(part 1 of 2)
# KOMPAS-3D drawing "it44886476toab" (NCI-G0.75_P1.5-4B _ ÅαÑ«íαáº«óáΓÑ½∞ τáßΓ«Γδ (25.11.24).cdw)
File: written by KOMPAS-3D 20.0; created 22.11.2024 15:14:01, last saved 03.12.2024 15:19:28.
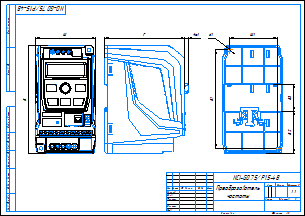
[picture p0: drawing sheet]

Sheet 1: A3, landscape

Document properties: Полное имя файла: P:\INSTART\Технический отдел\ОР\Прочие задачи\КД на номенклатурный ряд\КД на типоразмеры ПЧ\NCI\NCI-G0.75_P1.5-4B\NCI-G0.75_P1.5-4B _ Преобразователь частоты (25.11.24).cdw; Автор: admin

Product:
- Part/product: it44886476toab
    Масса: 2.32322
  - Body: Тело 2
      Масса: 0.00113358
  - Body: Тело 3
      Масса: 0.00113358
  - Body: Тело 4
      Масса: 0.000355433
  - Body: Тело 6
      Масса: 0.000355433
  - Body: Тело 7
      Масса: 0.000703761
  - Body: Тело 8
      Масса: 0.000703761
  - Body: Тело 10
      Масса: 0.0160396
  - Body: Тело 11
      Масса: 0.000703761
  - Body: Тело 13
      Масса: 0.000703761
  - Body: Тело 14
      Масса: 0.000703761
  - Body: Тело 18
      Масса: 0.0117014
  - Body: Тело 20
      Масса: 0.120334
  - Body: Тело 21
      Масса: 0.0864411
  - Body: Тело 22
      Масса: 0.0636504
  - Body: Тело 25
      Масса: 0.00135688
  - Body: Тело 26
      Масса: 0.00135688
  - Body: Тело 27
      Масса: 0.00135688
  - Body: Тело 30
      Масса: 0.000935996
  - Body: Тело 34
      Масса: 0.00831628
  - Body: Тело 36
      Масса: 0.0668131
  - Body: Тело 37
      Масса: 0.0343584
  - Body: Тело 39
      Масса: 0.0119524
  - Body: Тело 40
      Масса: 0.0119524
  - Body: Тело 42
      Масса: 0.0119524
  - Body: Тело 43
      Масса: 0.0119524
  - Body: Тело 46
      Масса: 0.0119034
  - Body: Тело 47
      Масса: 0.551587
  - Body: Тело 51
      Масса: 1.32696e-05
  - Body: Тело 54
      Масса: 1.32696e-05
  - Body: Тело 55
      Масса: 1.32696e-05
  - Body: Тело 56
      Масса: 1.32696e-05
  - Body: Тело 58
      Масса: 1.32696e-05
  - Body: Тело 61
      Масса: 1.32696e-05
  - Body: Тело 57
      Масса: 1.32696e-05
  - Body: Тело 63
      Масса: 1.65581e-05
  - Body: Тело 66
      Масса: 1.65581e-05
  - Body: Тело 67
      Масса: 1.65581e-05
  - Body: Тело 68
      Масса: 1.65581e-05
  - Body: Тело 69
      Масса: 1.65581e-05
  - Body: Тело 73
      Масса: 1.65581e-05
  - Body: Тело 48
      Масса: 0.00853877
  - Body: Тело 74
      Масса: 1.65581e-05
  - Body: Тело 78
      Масса: 1.65581e-05
  - Body: Тело 79
      Масса: 1.32696e-05
  - Body: Тело 80
      Масса: 1.32696e-05
  - Body: Тело 82
      Масса: 1.32696e-05
  - Body: Тело 83
      Масса: 1.32696e-05
  - Body: Тело 84
      Масса: 1.32696e-05
  - Body: Тело 87
      Масса: 0.000966482
  - Body: Тело 88
      Масса: 0.000873873
  - Body: Тело 15
      Масса: 0.000703761
  - Body: Тело 91
      Масса: 0.0246688
  - Body: Тело 92
      Масса: 3.83377e-05
  - Body: Тело 94
      Масса: 0.00554276
  - Body: Тело 96
      Масса: 0.00181049
  - Body: Тело 101
      Масса: 1.32696e-05
  - Body: Тело 90
      Масса: 0.000966482
  - Body: Тело 102
      Масса: 1.32696e-05
  - Body: Тело 104
      Масса: 1.32696e-05
  - Body: Тело 107
      Масса: 1.32696e-05
  - Body: Тело 108
      Масса: 1.32696e-05
  - Body: Тело 111
      Масса: 0.000194606
  - Body: Тело 115
      Масса: 0.000413213
  - Body: Тело 123
      Масса: 1.65581e-05
  - Body: Тело 127
      Масса: 1.32696e-05
  - Body: Тело 128
      Масса: 1.32696e-05
  - Body: Тело 129
      Масса: 1.32696e-05
  - Body: Тело 112
      Масса: 0.000413213
  - Body: Тело 130
      Масса: 1.32696e-05
  - Body: Тело 16
      Масса: 0.000703761
  - Body: Тело 131
      Масса: 1.32696e-05
  - Body: Тело 132
      Масса: 1.32696e-05
  - Body: Тело 133
      Масса: 1.32696e-05
  - Body: Тело 38
      Масса: 0.00631989
  - Body: Тело 135
      Масса: 1.32696e-05
  - Body: Тело 136
      Масса: 1.32696e-05
  - Body: Тело 142
      Масса: 0.000213463
  - Body: Тело 144
      Масса: 1.32696e-05
  - Body: Тело 62
      Масса: 1.32696e-05
  - Body: Тело 24
      Масса: 0.0110484
  - Body: Тело 147
      Масса: 1.32696e-05
  - Body: Тело 148
      Масса: 1.32696e-05
  - Body: Тело 154
      Масса: 1.32696e-05
  - Body: Тело 156
      Масса: 1.32696e-05
  - Body: Тело 158
      Масса: 1.32696e-05
  - Body: Тело 116
      Масса: 0.000413213
  - Body: Тело 159
      Масса: 1.32696e-05
  - Body: Тело 165
      Масса: 1.65581e-05
  - Body: Тело 166
      Масса: 1.32696e-05
  - Body: Тело 140
      Масса: 0.000213463
  - Body: Тело 169
      Масса: 1.32696e-05
  - Body: Тело 171
      Масса: 1.32696e-05
  - Body: Тело 153
      Масса: 1.32696e-05
  - Body: Тело 172
      Масса: 1.65581e-05
  - Body: Тело 173
      Масса: 1.32696e-05
  - Body: Тело 137
      Масса: 1.32696e-05
  - Body: Тело 45
      Масса: 0.0267013
  - Body: Тело 175
      Масса: 1.32696e-05
  - Body: Тело 177
      Масса: 1.32696e-05
  - Body: Тело 50
      Масса: 0.00101975
  - Body: Тело 44
      Масса: 0.0119524
  - Body: Тело 178
      Масса: 1.32696e-05
  - Body: Тело 179
      Масса: 1.32696e-05
  - Body: Тело 181
      Масса: 1.32696e-05
  - Body: Тело 182
      Масса: 1.32696e-05
  - Body: Тело 183
      Масса: 1.32696e-05
  - Body: Тело 188
      Масса: 1.32696e-05
  - Body: Тело 189
      Масса: 1.32696e-05
  - Body: Тело 192
      Масса: 1.32696e-05
  - Body: Тело 195
      Масса: 1.32696e-05
  - Body: Тело 197
      Масса: 1.32696e-05
  - Body: Тело 198
      Масса: 1.32696e-05
  - Body: Тело 199
      Масса: 1.32696e-05
  - Body: Тело 29
      Масса: 0.00135688
  - Body: Тело 201
      Масса: 1.32696e-05
  - Body: Тело 202
      Масса: 1.32696e-05
  - Body: Тело 205
      Масса: 1.32696e-05
  - Body: Тело 208
      Масса: 1.7366e-05
  - Body: Тело 209
      Масса: 1.32696e-05
  - Body: Тело 211
      Масса: 1.32696e-05
  - Body: Тело 212
      Масса: 1.32696e-05
  - Body: Тело 214
      Масса: 1.32696e-05
  - Body: Тело 9
      Масса: 0.000703761
  - Body: Тело 215
      Масса: 1.65581e-05
  - Body: Тело 217
      Масса: 1.32696e-05
  - Body: Тело 218
      Масса: 1.32696e-05
  - Body: Тело 219
      Масса: 1.32696e-05
  - Body: Тело 220
      Масса: 1.32696e-05
  - Body: Тело 221
      Масса: 1.65581e-05
  - Body: Тело 223
      Масса: 1.32696e-05
  - Body: Тело 162
      Масса: 1.65581e-05
  - Body: Тело 224
      Масса: 1.32696e-05
  - Body: Тело 228
      Масса: 1.32696e-05
  - Body: Тело 184
      Масса: 1.32696e-05
  - Body: Тело 230
      Масса: 1.32696e-05
  - Body: Тело 231
      Масса: 0.00398049
  - Body: Тело 232
      Масса: 5.48304e-05
  - Body: Тело 233
      Масса: 1.7366e-05
  - Body: Тело 1
      Масса: 0.00113358
  - Body: Тело 237
      Масса: 1.7366e-05
  - Body: Тело 141
      Масса: 0.000213463
  - Body: Тело 241
      Масса: 0.000424983
  - Body: Тело 65
      Масса: 1.65581e-05
  - Body: Тело 242
      Масса: 1.65581e-05
  - Body: Тело 243
      Масса: 1.65581e-05
  - Body: Тело 245
      Масса: 1.65581e-05
  - Body: Тело 234
      Масса: 1.7366e-05
  - Body: Тело 114
      Масса: 0.000413213
  - Body: Тело 19
      Масса: 0.0117014
  - Body: Тело 248
      Масса: 1.7366e-05
  - Body: Тело 249
      Масса: 1.7366e-05
  - Body: Тело 250
      Масса: 1.7366e-05
  - Body: Тело 254
      Масса: 1.32696e-05
  - Body: Тело 255
      Масса: 1.7366e-05
  - Body: Тело 119
      Масса: 0.000413213
  - Body: Тело 256
      Масса: 1.7366e-05
  - Body: Тело 167
      Масса: 1.32696e-05
  - Body: Тело 260
      Масса: 1.7366e-05
  - Body: Тело 261
      Масса: 3.83377e-05
  - Body: Тело 170
      Масса: 1.32696e-05
  - Body: Тело 463
      Масса: 0.000404362
  - Body: Тело 226
      Масса: 0.000413213
  - Body: Тело 464
      Масса: 0.00829425
  - Body: Тело 268
      Масса: 5.48304e-05
  - Body: Тело 467
      Масса: 0.00436982
  - Body: Тело 475
      Масса: 1.51773e-05
  - Body: Тело 451
      Масса: 6.34685e-05
  - Body: Тело 478
      Масса: 1.51773e-05
  - Body: Тело 465
      Масса: 0.00829114
  - Body: Тело 383
      Масса: 0.000340816
  - Body: Тело 125
      Масса: 1.65581e-05
  - Body: Тело 643
      Масса: 0.000158536
  - Body: Тело 514
      Масса: 1.51773e-05
  - Body: Тело 483
      Масса: 1.51773e-05
  - Body: Тело 486
      Масса: 0.000158536
  - Body: Тело 581
      Масса: 1.65581e-05
  - Body: Тело 490
      Масса: 1.51773e-05
  - Body: Тело 491
      Масса: 1.65581e-05
  - Body: Тело 433
      Масса: 0.000118347
  - Body: Тело 496
      Масса: 1.51773e-05
  - Body: Тело 437
      Масса: 0.00113358
  - Body: Тело 535
      Масса: 1.52051e-05
  - Body: Тело 498
      Масса: 1.51773e-05
  - Body: Тело 60
      Масса: 1.32696e-05
  - Body: Тело 369
      Масса: 1.32696e-05
  - Body: Тело 501
      Масса: 1.51773e-05
  - Body: Тело 503
      Масса: 1.51773e-05
  - Body: Тело 447
      Масса: 0.000307437
  - Body: Тело 187
      Масса: 1.32696e-05
  - Body: Тело 12
      Масса: 0.000703761
  - Body: Тело 507
      Масса: 1.51773e-05
  - Body: Тело 174
      Масса: 1.65581e-05
  - Body: Тело 587
      Масса: 1.32696e-05
  - Body: Тело 155
      Масса: 1.32696e-05
  - Body: Тело 512
      Масса: 1.51773e-05
  - Body: Тело 515
      Масса: 0.00507372
  - Body: Тело 510
      Масса: 1.51773e-05
  - Body: Тело 487
      Масса: 1.65581e-05
  - Body: Тело 432
      Масса: 0.000118347
  - Body: Тело 524
      Масса: 1.65581e-05
  - Body: Тело 637
      Масса: 1.51773e-05
  - Body: Тело 519
      Масса: 1.7366e-05
  - Body: Тело 427
      Масса: 1.32696e-05
  - Body: Тело 520
      Масса: 5.48304e-05
  - Body: Тело 326
      Масса: 1.32696e-05
  - Body: Тело 509
      Масса: 1.51773e-05
  - Body: Тело 571
      Масса: 0.00166679
  - Body: Тело 521
      Масса: 1.32696e-05
  - Body: Тело 522
      Масса: 1.65581e-05
  - Body: Тело 49
      Масса: 0.00944
  - Body: Тело 319
      Масса: 1.32696e-05
  - Body: Тело 458
      Масса: 1.51773e-05
  - Body: Тело 523
      Масса: 0.000255388
  - Body: Тело 191
      Масса: 1.32696e-05
  - Body: Тело 590
      Масса: 1.32696e-05
  - Body: Тело 599
      Масса: 7.12116e-06
  - Body: Тело 528
      Масса: 0.000141095
  - Body: Тело 64
      Масса: 1.65581e-05
  - Body: Тело 468
      Масса: 0.0253857
  - Body: Тело 216
      Масса: 0.000280294
  - Body: Тело 443
      Масса: 0.00113358
  - Body: Тело 239
      Масса: 5.48304e-05
  - Body: Тело 200
      Масса: 1.32696e-05
  - Body: Тело 579
      Масса: 0.00017125
  - Body: Тело 529
      Масса: 5.61948e-05
  - Body: Тело 493
      Масса: 1.51773e-05
  - Body: Тело 532
      Масса: 5.61948e-05
  - Body: Тело 343
      Масса: 0.00166679
  - Body: Тело 616
      Масса: 1.63919e-05
  - Body: Тело 462
      Масса: 0.000404362
  - Body: Тело 542
      Масса: 0.000158536
  - Body: Тело 543
      Масса: 0.000158536
  - Body: Тело 615
      Масса: 1.63919e-05
  - Body: Тело 149
      Масса: 1.32696e-05
  - Body: Тело 146
      Масса: 1.32696e-05
  - Body: Тело 469
      Масса: 0.0113891
  - Body: Тело 544
      Масса: 0.000158536
  - Body: Тело 295
      Масса: 1.65581e-05
  - Body: Тело 120
      Масса: 0.000413213
  - Body: Тело 352
      Масса: 2.90876e-05
  - Body: Тело 502
      Масса: 1.51773e-05
  - Body: Тело 461
      Масса: 0.000404362
  - Body: Тело 145
      Масса: 1.32696e-05
  - Body: Тело 545
      Масса: 1.51773e-05
  - Body: Тело 506
      Масса: 1.51773e-05
  - Body: Тело 71
      Масса: 1.65581e-05
  - Body: Тело 41
      Масса: 0.0119524
  - Body: Тело 547
      Масса: 0.000255388
  - Body: Тело 614
      Масса: 1.63919e-05
  - Body: Тело 257
      Масса: 1.7366e-05
  - Body: Тело 549
      Масса: 0.000255388
  - Body: Тело 204
      Масса: 1.32696e-05
  - Body: Тело 35
      Масса: 0.262997
  - Body: Тело 421
      Масса: 1.7366e-05
  - Body: Тело 258
      Масса: 1.7366e-05
  - Body: Тело 504
      Масса: 1.51773e-05
  - Body: Тело 366
      Масса: 1.7366e-05
  - Body: Тело 592
      Масса: 7.12116e-06
  - Body: Тело 32
      Масса: 0.0135217
  - Body: Тело 550
      Масса: 0.000255388
  - Body: Тело 157
      Масса: 1.32696e-05
  - Body: Тело 126
      Масса: 0.000512664
  - Body: Тело 314
      Масса: 1.7366e-05
  - Body: Тело 247
      Масса: 1.7366e-05
  - Body: Тело 23
      Масса: 0.0243258
  - Body: Тело 595
      Масса: 1.32696e-05
  - Body: Тело 534
      Масса: 1.32696e-05
  - Body: Тело 552
      Масса: 4.06595e-05
  - Body: Тело 176
      Масса: 1.32696e-05
  - Body: Тело 553
      Масса: 4.06595e-05
  - Body: Тело 28
      Масса: 0.00135688
  - Body: Тело 330
      Масса: 1.7366e-05
  - Body: Тело 190
      Масса: 1.32696e-05
  - Body: Тело 416
      Масса: 1.7366e-05
  - Body: Тело 435
      Масса: 0.00113358
  - Body: Тело 634
      Масса: 1.51773e-05
  - Body: Тело 555
      Масса: 0.00166679
  - Body: Тело 556
      Масса: 0.00166679
  - Body: Тело 602
      Масса: 5.61948e-05
  - Body: Тело 630
      Масса: 1.51773e-05
  - Body: Тело 558
      Масса: 0.00726683
  - Body: Тело 505
      Масса: 1.51773e-05
  - Body: Тело 500
      Масса: 1.51773e-05
  - Body: Тело 72
      Масса: 1.65581e-05
  - Body: Тело 279
      Масса: 1.32696e-05
  - Body: Тело 298
      Масса: 3.64495e-05
  - Body: Тело 168
      Масса: 1.32696e-05
  - Body: Тело 495
      Масса: 1.51773e-05
  - Body: Тело 336
      Масса: 3.64028e-05
  - Body: Тело 629
      Масса: 1.51773e-05
  - Body: Тело 263
      Масса: 1.7366e-05
  - Body: Тело 610
      Масса: 0.00166679
  - Body: Тело 609
      Масса: 1.7366e-05
  - Body: Тело 596
      Масса: 1.32696e-05
  - Body: Тело 538
      Масса: 1.51773e-05
  - Body: Тело 476
      Масса: 1.51773e-05
  - Body: Тело 227
      Масса: 1.32696e-05
  - Body: Тело 382
      Масса: 5.48304e-05
  - Body: Тело 470
      Масса: 0.00329329
  - Body: Тело 341
      Масса: 0.00166679
  - Body: Тело 426
      Масса: 1.32696e-05
  - Body: Тело 513
      Масса: 1.51773e-05
  - Body: Тело 236
      Масса: 1.7366e-05
  - Body: Тело 585
      Масса: 4.06595e-05
  - Body: Тело 649
      Масса: 0.00426189
  - Body: Тело 531
      Масса: 5.61948e-05
  - Body: Тело 627
      Масса: 0.000255388
  - Body: Тело 621
      Масса: 1.32696e-05
  - Body: Тело 349
      Масса: 1.7366e-05
  - Body: Тело 580
      Масса: 1.32696e-05
  - Body: Тело 631
      Масса: 1.51773e-05
  - Body: Тело 185
      Масса: 1.32696e-05
  - Body: Тело 117
      Масса: 0.000413213
  - Body: Тело 623
      Масса: 1.32696e-05
  - Body: Тело 605
      Масса: 5.61948e-05
  - Body: Тело 400
      Масса: 1.7366e-05
  - Body: Тело 139
      Масса: 0.000194606
  - Body: Тело 492
      Масса: 1.51773e-05
  - Body: Тело 612
      Масса: 0.000158536
  - Body: Тело 403
      Масса: 1.7366e-05
  - Body: Тело 460
      Масса: 3.90329e-05
  - Body: Тело 608
      Масса: 0.00166679
  - Body: Тело 635
      Масса: 1.65581e-05
  - Body: Тело 264
      Масса: 1.7366e-05
  - Body: Тело 646
      Масса: 0.000137594
  - Body: Тело 110
      Масса: 1.32696e-05
  - Body: Тело 302
      Масса: 1.65581e-05
  - Body: Тело 151
      Масса: 1.65581e-05
  - Body: Тело 497
      Масса: 1.51773e-05
  - Body: Тело 620
      Масса: 1.7366e-05
  - Body: Тело 518
      Масса: 0.00166679
  - Body: Тело 633
      Масса: 1.51773e-05
  - Body: Тело 564
      Масса: 4.06595e-05
  - Body: Тело 641
      Масса: 3.90329e-05
  - Body: Тело 494
      Масса: 1.51773e-05
  - Body: Тело 280
      Масса: 1.32696e-05
  - Body: Тело 81
      Масса: 1.32696e-05
  - Body: Тело 482
      Масса: 1.51773e-05
  - Body: Тело 594
      Масса: 1.32696e-05
  - Body: Тело 561
      Масса: 1.65581e-05
  - Body: Тело 253
      Масса: 1.7366e-05
  - Body: Тело 164
      Масса: 1.32696e-05
  - Body: Тело 525
      Масса: 0.000213463
  - Body: Тело 618
      Масса: 1.63919e-05
  - Body: Тело 642
      Масса: 3.90329e-05
  - Body: Тело 113
      Масса: 0.000413213
  - Body: Тело 546
      Масса: 0.000255388
  - Body: Тело 225
      Масса: 1.32696e-05
  - Body: Тело 138
      Масса: 2.23009e-05
  - Body: Тело 284
      Масса: 1.7366e-05
  - Body: Тело 485
      Масса: 0.000158536
  - Body: Тело 456
      Масса: 1.51773e-05
  - Body: Тело 489
      Масса: 1.51773e-05
  - Body: Тело 638
      Масса: 1.7366e-05
  - Body: Тело 563
      Масса: 4.06595e-05
  - Body: Тело 566
      Масса: 1.32696e-05
  - Body: Тело 160
      Масса: 1.32696e-05
  - Body: Тело 511
      Масса: 1.51773e-05
  - Body: Тело 541
      Масса: 0.000158536
  - Body: Тело 306
      Масса: 1.65581e-05
  - Body: Тело 356
      Масса: 1.65581e-05
  - Body: Тело 591
      Масса: 7.12116e-06
  - Body: Тело 313
      Масса: 1.7366e-05
  - Body: Тело 471
      Масса: 0.00329327
  - Body: Тело 289
      Масса: 1.7366e-05
  - Body: Тело 607
      Масса: 1.32696e-05
  - Body: Тело 603
      Масса: 5.61948e-05
  - Body: Тело 600
      Масса: 5.61948e-05
  - Body: Тело 121
      Масса: 0.000413213
  - Body: Тело 624
      Масса: 1.32696e-05
  - Body: Тело 527
      Масса: 0.000141095
  - Body: Тело 622
      Масса: 1.32696e-05
  - Body: Тело 484
      Масса: 0.000158536
  - Body: Тело 601
      Масса: 5.61948e-05
  - Body: Тело 296
      Масса: 3.6965e-05
  - Body: Тело 540
      Масса: 1.51773e-05
  - Body: Тело 210
      Масса: 1.32696e-05
  - Body: Тело 611
      Масса: 0.000158536
  - Body: Тело 161
      Масса: 1.32696e-05
  - Body: Тело 650
      Масса: 0.00426189
  - Body: Тело 604
      Масса: 5.61948e-05
  - Body: Тело 342
      Масса: 0.00166679
  - Body: Тело 251
      Масса: 1.7366e-05
  - Body: Тело 194
      Масса: 1.32696e-05
  - Body: Тело 568
      Масса: 1.32696e-05
  - Body: Тело 150
      Масса: 1.32696e-05
  - Body: Тело 640
      Масса: 1.63919e-05
  - Body: Тело 440
      Масса: 0.000355433
  - Body: Тело 499
      Масса: 1.51773e-05
  - Body: Тело 589
      Масса: 1.32696e-05
  - Body: Тело 361
      Масса: 1.32696e-05
  - Body: Тело 619
      Масса: 1.32696e-05
  - Body: Тело 405
      Масса: 1.32696e-05
  - Body: Тело 551
      Масса: 0.000255388
  - Body: Тело 598
      Масса: 7.12116e-06
  - Body: Тело 583
      Масса: 4.06595e-05
  - Body: Тело 411
      Масса: 5.48304e-05
  - Body: Тело 367
      Масса: 1.32696e-05
  - Body: Тело 488
      Масса: 1.51773e-05
  - Body: Тело 163
      Масса: 1.32696e-05
  - Body: Тело 109
      Масса: 1.32696e-05
  - Body: Тело 408
      Масса: 5.48304e-05
  - Body: Тело 593
      Масса: 1.32696e-05
  - Body: Тело 387
      Масса: 1.32696e-05
  - Body: Тело 613
      Масса: 1.63919e-05
  - Body: Тело 597
      Масса: 7.12116e-06
  - Body: Тело 118
      Масса: 0.000413213
  - Body: Тело 565
      Масса: 4.06595e-05
  - Body: Тело 632
      Масса: 1.51773e-05
  - Body: Тело 379
      Масса: 1.32696e-05
  - Body: Тело 562
      Масса: 0.000382752
  - Body: Тело 262
      Масса: 1.7366e-05
  - Body: Тело 586
      Масса: 1.32696e-05
  - Body: Тело 647
      Масса: 0.00426189
  - Body: Тело 533
      Масса: 5.61948e-05
  - Body: Тело 472
      Масса: 0.00329327
  - Body: Тело 409
      Масса: 5.48304e-05
  - Body: Тело 548
      Масса: 2.98222e-05
  - Body: Тело 474
      Масса: 1.51773e-05
  - Body: Тело 363
      Масса: 1.32696e-05
  - Body: Тело 276
      Масса: 1.7366e-05
  - Body: Тело 588
      Масса: 1.32696e-05
  - Body: Тело 70
      Масса: 1.65581e-05
  - Body: Тело 584
      Масса: 4.06595e-05
  - Body: Тело 644
      Масса: 0.000158536
  - Body: Тело 625
      Масса: 1.32696e-05
  - Body: Тело 213
      Масса: 1.32696e-05
  - Body: Тело 275
      Масса: 1.7366e-05
  - Body: Тело 320
      Масса: 1.32696e-05
  - Body: Тело 399
      Масса: 1.32696e-05
  - Body: Тело 574
      Масса: 4.06595e-05
  - Body: Тело 85
      Масса: 1.32696e-05
  - Body: Тело 576
      Масса: 1.32696e-05
  - Body: Тело 575
      Масса: 1.32696e-05
  - Body: Тело 376
      Масса: 1.32696e-05
  - Body: Тело 316
      Масса: 1.32696e-05
  - Body: Тело 449
      Масса: 0.0658364
  - Body: Тело 152
      Масса: 1.32696e-05
  - Body: Тело 559
      Масса: 1.65581e-05
  - Body: Тело 645
      Масса: 1.32696e-05
  - Body: Тело 207
      Масса: 1.32696e-05
  - Body: Тело 567
      Масса: 1.32696e-05
  - Body: Тело 572
      Масса: 1.32696e-05
  - Body: Тело 203
      Масса: 1.32696e-05
  - Body: Тело 582
      Масса: 1.65581e-05
  - Body: Тело 134
      Масса: 1.32696e-05
  - Body: Тело 626
      Масса: 1.32696e-05
  - Body: Тело 578
      Масса: 1.32696e-05
  - Body: Тело 569
      Масса: 1.32696e-05
  - Body: Тело 557
      Масса: 0.00166679
  - Body: Тело 459
      Масса: 3.90329e-05
  - Body: Тело 457
      Масса: 1.51773e-05
  - Body: Тело 539
      Масса: 1.51773e-05
  - Body: Тело 455
      Масса: 1.51773e-05
  - Body: Тело 428
      Масса: 0.146258
  - Body: Тело 454
      Масса: 0.000382752
  - Body: Тело 453
      Масса: 1.63919e-05
  - Body: Тело 417
      Масса: 1.32696e-05
  - Body: Тело 517
      Масса: 0.00106884
  - Body: Тело 418
      Масса: 1.7366e-05
  - Body: Тело 401
      Масса: 1.32696e-05
  - Body: Тело 53
      Масса: 1.32696e-05
  - Body: Тело 452
      Масса: 1.63919e-05
  - Body: Тело 315
      Масса: 1.7366e-05
  - Body: Тело 222
      Масса: 1.32696e-05
  - Body: Тело 450
      Масса: 6.34685e-05
  - Body: Тело 481
      Масса: 1.51773e-05
  - Body: Тело 448
      Масса: 0.000307437
  - Body: Тело 193
      Масса: 1.32696e-05
  - Body: Тело 392
      Масса: 1.32696e-05
  - Body: Тело 577
      Масса: 1.7366e-05
  - Body: Тело 508
      Масса: 1.51773e-05
  - Body: Тело 106
      Масса: 1.32696e-05
  - Body: Тело 438
      Масса: 0.000355433
  - Body: Тело 445
      Масса: 0.00113358
  - Body: Тело 246
      Масса: 1.65581e-05
  - Body: Тело 444
      Масса: 0.000355433
  - Body: Тело 554
      Масса: 4.06595e-05
  - Body: Тело 442
      Масса: 0.000355433
  - Body: Тело 441
      Масса: 0.00113358
  - Body: Тело 323
      Масса: 1.32696e-05
  - Body: Тело 606
      Масса: 0.000137594
  - Body: Тело 439
      Масса: 0.00113358
  - Body: Тело 436
      Масса: 0.000355433
  - Body: Тело 344
      Масса: 1.32696e-05
  - Body: Тело 124
      Масса: 1.65581e-05
  - Body: Тело 5
      Масса: 0.000355433
  - Body: Тело 434
      Масса: 0.000355433
  - Body: Тело 329
      Масса: 1.32696e-05
  - Body: Тело 364
      Масса: 1.32696e-05
  - Body: Тело 431
      Масса: 0.146258
  - Body: Тело 345
      Масса: 1.32696e-05
  - Body: Тело 350
      Масса: 1.7366e-05
  - Body: Тело 430
      Масса: 0.146258
  - Body: Тело 334
      Масса: 1.7366e-05
  - Body: Тело 429
      Масса: 0.146258
  - Body: Тело 206
      Масса: 1.32696e-05
  - Body: Тело 271
      Масса: 1.32696e-05
  - Body: Тело 365
      Масса: 1.32696e-05
  - Body: Тело 425
      Масса: 1.32696e-05
  - Body: Тело 305
      Масса: 1.65581e-05
  - Body: Тело 98
      Масса: 1.65581e-05
  - Body: Тело 424
      Масса: 1.7366e-05
  - Body: Тело 423
      Масса: 1.32696e-05
  - Body: Тело 381
      Масса: 1.7366e-05
  - Body: Тело 422
      Масса: 5.48304e-05
  - Body: Тело 186
      Масса: 1.32696e-05
  - Body: Тело 420
      Масса: 1.7366e-05
  - Body: Тело 648
      Масса: 0.00426189
  - Body: Тело 419
      Масса: 1.32696e-05
  - Body: Тело 235
      Масса: 1.7366e-05
  - Body: Тело 415
      Масса: 1.7366e-05
  - Body: Тело 537
      Масса: 0.000158536
  - Body: Тело 414
      Масса: 1.32696e-05
  - Body: Тело 413
      Масса: 1.32696e-05
  - Body: Тело 412
      Масса: 1.7366e-05
  - Body: Тело 636
      Масса: 1.65581e-05
  - Body: Тело 410
      Масса: 5.48304e-05
  - Body: Тело 97
      Масса: 0.0015961
  - Body: Тело 407
      Масса: 5.48304e-05
  - Body: Тело 52
      Масса: 1.32696e-05
  - Body: Тело 393
      Масса: 1.32696e-05
  - Body: Тело 406
      Масса: 1.65581e-05
  - Body: Тело 89
      Масса: 0.00142218
  - Body: Тело 404
      Масса: 1.32696e-05
  - Body: Тело 339
      Масса: 1.32696e-05
  - Body: Тело 59
      Масса: 1.32696e-05
  - Body: Тело 402
      Масса: 1.7366e-05
  - Body: Тело 479
      Масса: 1.51773e-05
  - Body: Тело 398
      Масса: 1.65581e-05
  - Body: Тело 397
      Масса: 1.32696e-05
  - Body: Тело 396
      Масса: 1.7366e-05
  - Body: Тело 354
      Масса: 0.000213463
  - Body: Тело 395
      Масса: 1.32696e-05
  - Body: Тело 394
      Масса: 1.32696e-05
  - Body: Тело 143
      Масса: 1.32696e-05
  - Body: Тело 390
      Масса: 1.65581e-05
  - Body: Тело 93
      Масса: 3.83377e-05
  - Body: Тело 389
      Масса: 1.65581e-05
  - Body: Тело 388
      Масса: 1.32696e-05
  - Body: Тело 229
      Масса: 1.32696e-05
  - Body: Тело 386
      Масса: 1.32696e-05
  - Body: Тело 291
      Масса: 0.000213463
  - Body: Тело 385
      Масса: 1.32696e-05
  - Body: Тело 639
      Масса: 1.63919e-05
  - Body: Тело 380
      Масса: 1.32696e-05
  - Body: Тело 322
      Масса: 1.32696e-05
  - Body: Тело 372
      Масса: 1.7366e-05
  - Body: Тело 95
      Масса: 0.000935996
  - Body: Тело 378
      Масса: 0.000413213
  - Body: Тело 259
      Масса: 1.7366e-05
  - Body: Тело 76
      Масса: 1.65581e-05
  - Body: Тело 351
      Масса: 2.90876e-05
  - Body: Тело 375
      Масса: 1.32696e-05
  - Body: Тело 373
      Масса: 1.32696e-05
  - Body: Тело 75
      Масса: 1.32696e-05
  - Body: Тело 371
      Масса: 1.7366e-05
  - Body: Тело 628
      Масса: 1.51773e-05
  - Body: Тело 333
      Масса: 1.32696e-05
  - Body: Тело 370
      Масса: 1.32696e-05
  - Body: Тело 368
      Масса: 1.32696e-05
  - Body: Тело 310
      Масса: 1.7366e-05
  - Body: Тело 86
      Масса: 1.32696e-05
  - Body: Тело 286
      Масса: 1.7366e-05
  - Body: Тело 359
      Масса: 1.7366e-05
  - Body: Тело 358
      Масса: 5.48304e-05
  - Body: Тело 466
      Масса: 0.00829114
  - Body: Тело 355
      Масса: 5.48304e-05
  - Body: Тело 353
      Масса: 1.7366e-05
  - Body: Тело 362
      Масса: 1.32696e-05
  - Body: Тело 281
      Масса: 1.32696e-05
  - Body: Тело 335
      Масса: 1.32696e-05
  - Body: Тело 346
      Масса: 1.32696e-05
  - Body: Тело 357
      Масса: 1.65581e-05
  - Body: Тело 196
      Масса: 1.32696e-05
  - Body: Тело 340
      Масса: 1.32696e-05
  - Body: Тело 570
      Масса: 4.06595e-05
  - Body: Тело 338
      Масса: 1.7366e-05
  - Body: Тело 337
      Масса: 1.7366e-05
  - Body: Тело 446
      Масса: 0.000307437
  - Body: Тело 332
      Масса: 1.7366e-05
  - Body: Тело 331
      Масса: 1.7366e-05
  - Body: Тело 301
      Масса: 1.65581e-05
  - Body: Тело 328
      Масса: 1.7366e-05
  - Body: Тело 105
      Масса: 1.32696e-05
  - Body: Тело 100
      Масса: 1.65581e-05
  - Body: Тело 31
      Масса: 0.0078835
  - Body: Тело 327
      Масса: 1.32696e-05
  - Body: Тело 617
      Масса: 1.63919e-05
  - Body: Тело 99
      Масса: 1.65581e-05
  - Body: Тело 325
      Масса: 1.32696e-05
  - Body: Тело 293
      Масса: 5.48304e-05
  - Body: Тело 288
      Масса: 1.7366e-05
  - Body: Тело 480
      Масса: 1.51773e-05
  - Body: Тело 324
      Масса: 1.32696e-05
  - Body: Тело 321
      Масса: 1.32696e-05
  - Body: Тело 318
      Масса: 1.32696e-05
  - Body: Тело 317
      Масса: 1.32696e-05
  - Body: Тело 312
      Масса: 5.48304e-05
  - Body: Тело 560
      Масса: 1.65581e-05
  - Body: Тело 122
      Масса: 1.65581e-05
  - Body: Тело 311
      Масса: 5.48304e-05
  - Body: Тело 473
      Масса: 0.00425494
  - Body: Тело 309
      Масса: 1.32696e-05
  - Body: Тело 240
      Масса: 1.7366e-05
  - Body: Тело 180
      Масса: 1.32696e-05
  - Body: Тело 308
      Масса: 0.000413213
  - Body: Тело 307
      Масса: 0.000213463
  - Body: Тело 304
      Масса: 1.65581e-05
  - Body: Тело 347
      Масса: 1.32696e-05
  - Body: Тело 360
      Масса: 1.32696e-05
  - Body: Тело 384
      Масса: 5.48304e-05
  - Body: Тело 516
      Масса: 0.00507377
  - Body: Тело 303
      Масса: 1.65581e-05
  - Body: Тело 300
      Масса: 1.65581e-05
  - Body: Тело 283
      Масса: 1.7366e-05
  - Body: Тело 299
      Масса: 3.64028e-05
  - Body: Тело 297
      Масса: 3.64631e-05
  - Body: Тело 294
      Масса: 0.000413213
  - Body: Тело 252
      Масса: 5.48304e-05
  - Body: Тело 33
      Масса: 0.00516019
  - Body: Тело 292
      Масса: 1.7366e-05
  - Body: Тело 269
      Масса: 5.48304e-05
  - Body: Тело 290
      Масса: 0.000413213
  - Body: Тело 287
      Масса: 1.32696e-05
  - Body: Тело 285
      Масса: 5.48304e-05
  - Body: Тело 391
      Масса: 1.32696e-05
  - Body: Тело 526
      Масса: 5.61948e-05
  - Body: Тело 477
      Масса: 1.51773e-05
  - Body: Тело 282
      Масса: 1.7366e-05
  - Body: Тело 278
      Масса: 1.7366e-05
  - Body: Тело 530
      Масса: 5.61948e-05
  - Body: Тело 277
      Масса: 1.7366e-05
  - Body: Тело 274
      Масса: 1.7366e-05
  - Body: Тело 238
      Масса: 1.7366e-05
  - Body: Тело 273
      Масса: 5.48304e-05
  - Body: Тело 272
      Масса: 1.7366e-05
  - Body: Тело 377
      Масса: 1.65581e-05
  - Body: Тело 536
      Масса: 0.000158536
  - Body: Тело 244
      Масса: 1.65581e-05
  - Body: Тело 77
      Масса: 1.32696e-05
  - Body: Тело 270
      Масса: 1.7366e-05
  - Body: Тело 348
      Масса: 1.32696e-05
  - Body: Тело 573
      Масса: 4.06595e-05
  - Body: Тело 103
      Масса: 1.32696e-05
  - Body: Тело 267
      Масса: 1.7366e-05
  - Body: Тело 266
      Масса: 1.7366e-05
  - Body: Тело 265
      Масса: 1.32696e-05
  - Body: Тело 374
      Масса: 5.48304e-05
  - Body: Тело 17
      Масса: 0.0117014

Title block, sheet 1: Наименование: Преобразователь / частоты; designation: NCI-G0.75/P1.5-4B; Количество листов документа: 1; Форматы листов документа: A3; stored path: P:\INSTART\Технический отдел\ОР\Прочие задачи\КД на номенклатурный ряд\КД на типоразмеры ПЧ\NCI\NCI-G0.75_P1.5-4B\NCI-G0.75_P1.5-4B _ Преобразователь частоты.cdw

Referenced files in P:\INSTART\Технический отдел\ОР\Уралов\Проверка КД\: KD600M-4T2R2-20240807.m3d
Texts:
  Кривая без истории:10000
  Кривая без истории:10001
  Кривая без истории:10002
  Кривая без истории:10003
  Кривая без истории:10004
  Кривая без истории:10005
  Кривая без истории:10006
  Кривая без истории:10007
  Кривая без истории:10008
  Кривая без истории:10009
  Кривая без истории:10010
  Кривая без истории:10011
  Кривая без истории:10012
  Кривая без истории:10013
  Кривая без истории:10014
  Кривая без истории:10015
  Кривая без истории:10016
  Кривая без истории:10017
  Кривая без истории:10018
  Кривая без истории:10019
  Кривая без истории:10020
  Кривая без истории:10021
  Кривая без истории:10022
  Кривая без истории:10023
  Кривая без истории:10024
  Кривая без истории:10025
  Кривая без истории:10026
  Кривая без истории:10027
  Кривая без истории:10028
  Кривая без истории:10029
  Кривая без истории:10030
  Кривая без истории:10031
  Кривая без истории:10032
  Кривая без истории:10033
  Кривая без истории:10034
  Кривая без истории:10035
  Кривая без истории:10036
  Кривая без истории:10037
  Кривая без истории:10038
  Кривая без истории:10039
  Кривая без истории:10040
  Кривая без истории:10041
  Кривая без истории:10042
  Кривая без истории:10043
  Кривая без истории:10044
  Кривая без истории:10045
  Кривая без истории:10046
  Кривая без истории:10047
  Кривая без истории:10048
  Кривая без истории:10049
  Кривая без истории:10050
  Кривая без истории:10051
  Кривая без истории:10052
  Кривая без истории:10053
  Кривая без истории:10054
  Кривая без истории:10055
  Кривая без истории:10056
  Кривая без истории:10057
  Кривая без истории:10058
  Кривая без истории:10059
  Кривая без истории:10060
  Кривая без истории:10061
  Кривая без истории:10062
  Кривая без истории:10063
  Кривая без истории:10064
  Кривая без истории:10065
  Кривая без истории:10066
  Кривая без истории:10067
  Кривая без истории:10068
  Кривая без истории:10069
  Кривая без истории:10070
  Кривая без истории:10071
  Кривая без истории:10072
  Кривая без истории:10073
  Кривая без истории:10074
  Кривая без истории:10075
  Кривая без истории:10076
  Кривая без истории:10077
  Кривая без истории:10078
  Кривая без истории:10079
  Кривая без истории:10080
  Кривая без истории:10081
  Кривая без истории:10082
  Кривая без истории:10083
  Кривая без истории:10084
  Кривая без истории:10085
  Кривая без истории:10086
  Кривая без истории:10087
  Кривая без истории:10088
  Кривая без истории:10089
  Кривая без истории:10090
  Кривая без истории:10091
  Кривая без истории:10092
  Кривая без истории:10093
  Кривая без истории:10094
  Кривая без истории:10095
  Кривая без истории:10096
  Кривая без истории:10097
  Кривая без истории:10098
  Кривая без истории:10099
  Кривая без истории:10100
  Кривая без истории:10101
  Кривая без истории:10102
  Кривая без истории:10103
  Кривая без истории:10104
  Кривая без истории:10105
  Кривая без истории:10106
  Кривая без истории:10107
  Кривая без истории:10108
  Кривая без истории:10109
  Кривая без истории:10110
  Кривая без истории:10111
  Кривая без истории:10112
  Кривая без истории:10113
  Кривая без истории:10114
  Кривая без истории:10115
  Кривая без истории:10116
  Кривая без истории:10117
  Кривая без истории:10118
  Кривая без истории:10119
  Кривая без истории:10120
  Кривая без истории:10121
  Кривая без истории:10122
  Кривая без истории:10123
  Кривая без истории:10124
  Кривая без истории:10125
  Кривая без истории:10126
  Кривая без истории:10127
  Кривая без истории:10128
  Кривая без истории:10129
  Кривая без истории:10130
  Кривая без истории:10131
  Кривая без истории:10132
  Кривая без истории:10133
  Кривая без истории:10134
  Кривая без истории:10135
  Кривая без истории:10136
  Кривая без истории:10137
  Кривая без истории:10138
  Кривая без истории:10139
  Кривая без истории:10140
  Кривая без истории:10141
  Кривая без истории:10142
  Кривая без истории:10143
  Кривая без истории:10144
  Кривая без истории:10145
  Кривая без истории:10146
  Кривая без истории:10147
  Кривая без истории:10148
  Кривая без истории:10149
  Кривая без истории:10150
  Кривая без истории:10151
  Кривая без истории:10152
  Кривая без истории:10153
  Кривая без истории:10154
  Кривая без истории:10155
  Кривая без истории:10156
  Кривая без истории:10157
  Кривая без истории:10158
  Кривая без истории:10159
  Кривая без истории:10160
  Кривая без истории:10161
  Кривая без истории:10162
  Кривая без истории:10163
  Кривая без истории:10164
  Кривая без истории:10165
  Кривая без истории:10166
  Кривая без истории:10167
  Кривая без истории:10168
  Кривая без истории:10169
  Кривая без истории:10170
  Кривая без истории:10171
  Кривая без истории:10172
  Кривая без истории:10173
  Кривая без истории:10174
  Кривая без истории:10175
  Кривая без истории:10176
  Кривая без истории:10177
  Кривая без истории:10178
  Кривая без истории:10179
  Кривая без истории:10180
  Кривая без истории:10181
  Кривая без истории:10182
  Кривая без истории:10183
  Кривая без истории:10184
  Кривая без истории:10185
  Кривая без истории:10186
  Кривая без истории:10187
  Кривая без истории:10188
  Кривая без истории:10189
  Кривая без истории:10190
  Кривая без истории:10191
  Кривая без истории:10192
  Кривая без истории:10193
  Кривая без истории:10194
  Кривая без истории:10195
  Кривая без истории:10196
  Кривая без истории:10197
  Кривая без истории:10198
  Кривая без истории:10199
  Кривая без истории:10200
  Кривая без истории:10201
  Кривая без истории:10202
  Кривая без истории:10203
  Кривая без истории:10204
  Кривая без истории:10205
  Кривая без истории:10206
  Кривая без истории:10207
  Кривая без истории:10208
  Кривая без истории:10209
  Кривая без истории:10210
  Кривая без истории:10211
  Кривая без истории:10212
  Кривая без истории:10213
  Кривая без истории:10214
  Кривая без истории:10215
  Кривая без истории:10216
  Кривая без истории:10217
  Кривая без истории:10218
  Кривая без истории:10219
  Кривая без истории:10220
  Кривая без истории:10221
  Кривая без истории:10222
  Кривая без истории:10223
  Кривая без истории:10224
  Кривая без истории:10225
  Кривая без истории:10226
  Кривая без истории:10227
  Кривая без истории:10228
  Кривая без истории:10229
  Кривая без истории:10230
  Кривая без истории:10231
  Кривая без истории:10232
  Кривая без истории:10233
  Кривая без истории:10234
  Кривая без истории:10235
  Кривая без истории:10236
  Кривая без истории:10237
  Кривая без истории:10238
  Кривая без истории:10239
  Кривая без истории:10240
  Кривая без истории:10241
  Кривая без истории:10242
  Кривая без истории:10243
  Кривая без истории:10244
  Кривая без истории:10245
  Кривая без истории:10246
  Кривая без истории:10247
  Кривая без истории:10248
  Кривая без истории:10249
  Кривая без истории:10250
  Кривая без истории:10251
  Кривая без истории:10252
  Кривая без истории:10253
  Кривая без истории:10254
  Кривая без истории:10255
  Кривая без истории:10256
  Кривая без истории:10257
  Кривая без истории:10258
  Кривая без истории:10259
  Кривая без истории:10260
  Кривая без истории:10261
  Кривая без истории:10262
  Кривая без истории:10263
  Кривая без истории:10264
  Кривая без истории:10265
  Кривая без истории:10266
  Кривая без истории:10267
  Кривая без истории:10268
  Кривая без истории:10269
  Кривая без истории:10270
  Кривая без истории:10271
  Кривая без истории:10272
  Кривая без истории:10273
  Кривая без истории:10274
  Кривая без истории:10275
  Кривая без истории:10276
  Кривая без истории:10277
  Кривая без истории:10278
  Кривая без истории:10279
  Кривая без истории:10280
  Кривая без истории:10281
  Кривая без истории:10282
  Кривая без истории:10283
  Кривая без истории:10284
  Кривая без истории:10285
  Кривая без истории:10286
  Кривая без истории:10287
  Кривая без истории:10288
  Кривая без истории:10289
  Кривая без истории:10290
  Кривая без истории:10291
  Кривая без истории:10292
  Кривая без истории:10293
  Кривая без истории:10294
  Кривая без истории:10295
  Кривая без истории:10296
  Кривая без истории:10297
  Кривая без истории:10298
  Кривая без истории:10299
  Кривая без истории:10300
  Кривая без истории:10301
  Кривая без истории:10302
  Кривая без истории:10303
  Кривая без истории:10304
  Кривая без истории:10305
  Кривая без истории:10306
  Кривая без истории:10307
  Кривая без истории:10308
  Кривая без истории:10309
  Кривая без истории:10310
  Кривая без истории:10311
  Кривая без истории:10312
  Кривая без истории:10313
  Кривая без истории:10314
  Кривая без истории:10315
  Кривая без истории:10316
  Кривая без истории:10317
  Кривая без истории:10318
  Кривая без истории:10319
  Кривая без истории:10320
  Кривая без истории:10321
  Кривая без истории:10322
  Кривая без истории:10323
  Кривая без истории:10324
  Кривая без истории:10325
  Кривая без истории:10326
  Кривая без истории:10327
  Кривая без истории:10328
  Кривая без истории:10329
  Кривая без истории:10330
  Кривая без истории:10331
  Кривая без истории:10332
  Кривая без истории:10333
  Кривая без истории:10334
  Кривая без истории:10335
  Кривая без истории:10336
  Кривая без истории:10337
  Кривая без истории:10338
  Кривая без истории:10339
  Кривая без истории:10340
  Кривая без истории:10341
  Кривая без истории:10342
  Кривая без истории:10343
  Кривая без истории:10344
  Кривая без истории:10345
  Кривая без истории:10346
  Кривая без истории:10347
  Кривая без истории:10348
  Кривая без истории:10349
  Кривая без истории:10350
  Кривая без истории:10351
  Кривая без истории:10352
  Кривая без истории:10353
  Кривая без истории:10354
  Кривая без истории:10355
  Кривая без истории:10356
  Кривая без истории:10357
  Кривая без истории:10358
  Кривая без истории:10359
  Кривая без истории:10360
  Кривая без истории:10361
  Кривая без истории:10362
  Кривая без истории:10363
  Кривая без истории:10364
  Кривая без истории:10365
  Кривая без истории:10366
  Кривая без истории:10367
  Кривая без истории:10368
  Кривая без истории:10369
  Кривая без истории:10370
  Кривая без истории:10371
  Кривая без истории:10372
  Кривая без истории:10373
  Кривая без истории:10374
  Кривая без истории:10375
  Кривая без истории:10376
  Кривая без истории:10377
  Кривая без истории:10378
  Кривая без истории:10379
  Кривая без истории:10380
  Кривая без истории:10381
  Кривая без истории:10382
  Кривая без истории:10383
  Кривая без истории:10384
  Кривая без истории:10385
  Кривая без истории:10386
  Кривая без истории:10387
  Кривая без истории:10388
  Кривая без истории:10389
  Кривая без истории:10390
  Кривая без истории:10391
  Кривая без истории:10392
  Кривая без истории:10393
  Кривая без истории:10394
  Кривая без истории:10395
  Кривая без истории:10396
  Кривая без истории:10397
  Кривая без истории:10398
  Кривая без истории:10399
  Кривая без истории:10400
  Кривая без истории:10401
  Кривая без истории:10402
  Кривая без истории:10403
  Кривая без истории:10404
  Кривая без истории:10405
  Кривая без истории:10406
  Кривая без истории:10407
  Кривая без истории:10408
  Кривая без истории:10409
  Кривая без истории:10410
  Кривая без истории:10411
  Кривая без истории:10412
  Кривая без истории:10413
  Кривая без истории:10414
  Кривая без истории:10415
  Кривая без истории:10416
  Кривая без истории:10417
  Кривая без истории:10418
  Кривая без истории:10419
  Кривая без истории:10420
  Кривая без истории:10421
  Кривая без истории:10422
  Кривая без истории:10423
  Кривая без истории:10424
  Кривая без истории:10425
  Кривая без истории:10426
  Кривая без истории:10427
  Кривая без истории:10428
  Кривая без истории:10429
  Кривая без истории:10430
  Кривая без истории:10431
  Кривая без истории:10432
  Кривая без истории:10433
  Кривая без истории:10434
  Кривая без истории:10435
  Кривая без истории:10436
  Кривая без истории:10437
  Кривая без истории:10438
  Кривая без истории:10439
  Кривая без истории:10440
  Кривая без истории:10441
  Кривая без истории:10442
  Кривая без истории:10443
  Кривая без истории:10444
  Кривая без истории:10445
  Кривая без истории:10446
  Кривая без истории:10447
  Кривая без истории:10448
  Кривая без истории:10449
  Кривая без истории:10450
  Кривая без истории:10451
  Кривая без истории:10452
  Кривая без истории:10453
  Кривая без истории:10454
  Кривая без истории:10455
  Кривая без истории:10456
  Кривая без истории:10457
  Кривая без истории:10458
  Кривая без истории:10459
  Кривая без истории:10460
  Кривая без истории:10461
  Кривая без истории:10462
  Кривая без истории:10463
  Кривая без истории:10464
  Кривая без истории:10465
  Кривая без истории:10466
  Кривая без истории:10467
  Кривая без истории:10468
  Кривая без истории:10469
  Кривая без истории:10470
  Кривая без истории:10471
  Кривая без истории:10472
  Кривая без истории:10473
  Кривая без истории:10474
  Кривая без истории:10475
  Кривая без истории:10476
  Кривая без истории:10477
  Кривая без истории:10478
  Кривая без истории:10479
  Кривая без истории:10480
  Кривая без истории:10481
  Кривая без истории:10482
  Кривая без истории:10483
  Кривая без истории:10484
  Кривая без истории:10485
  Кривая без истории:10486
  Кривая без истории:10487
  Кривая без истории:10488
  Кривая без истории:10489
  Кривая без истории:10490
  Кривая без истории:10491
  Кривая без истории:10492
  Кривая без истории:10493
  Кривая без истории:10494
  Кривая без истории:10495
  Кривая без истории:10496
  Кривая без истории:10497
  Кривая без истории:10498
  Кривая без истории:10499
  Кривая без истории:10500
  Кривая без истории:10501
  Кривая без истории:10502
  Кривая без истории:10503
  Кривая без истории:10504
  Кривая без истории:10505
  Кривая без истории:10506
  Кривая без истории:10507
  Кривая без истории:10508
  Кривая без истории:10509
  Кривая без истории:10510
  Кривая без истории:10511
  Кривая без истории:10512
  Кривая без истории:10513
  Кривая без истории:10514
  Кривая без истории:10515
  Кривая без истории:10516
  Кривая без истории:10517
  Кривая без истории:10518
  Кривая без истории:10519
  Кривая без истории:10520
  Кривая без истории:10521
  Кривая без истории:10522
  Кривая без истории:10523
  Кривая без истории:10524
  Кривая без истории:10525
  Кривая без истории:10526
  Кривая без истории:10527
  Кривая без истории:10528
  Кривая без истории:10529
  Кривая без истории:10530
  Кривая без истории:10531
  Кривая без истории:10532
  Кривая без истории:10533
  Кривая без истории:10534
  Кривая без истории:10535
  Кривая без истории:10536
  Кривая без истории:10537
  Кривая без истории:10538
  Кривая без истории:10539
  Кривая без истории:10540
  Кривая без истории:10541
  Кривая без истории:10542
  Кривая без истории:10543
  Кривая без истории:10544
  Кривая без истории:10545
  Кривая без истории:10546
  Кривая без истории:10547
  Кривая без истории:10548
  Кривая без истории:10549
  Кривая без истории:10550
  Кривая без истории:10551
  Кривая без истории:10552
  Кривая без истории:10553
  Кривая без истории:10554
  Кривая без истории:10555
  Кривая без истории:10556
  Кривая без истории:10557
  Кривая без истории:10558
  Кривая без истории:10559
  Кривая без истории:10560
  Кривая без истории:10561
  Кривая без истории:10562
  Кривая без истории:10563
  Кривая без истории:10564
  Кривая без истории:10565
  Кривая без истории:10566
  Кривая без истории:10567
  Кривая без истории:10568
  Кривая без истории:10569
  Кривая без истории:10570
  Кривая без истории:10571
  Кривая без истории:10572
  Кривая без истории:10573
  Кривая без истории:10574
  Кривая без истории:10575
  Кривая без истории:10576
  Кривая без истории:10577
  Кривая без истории:10578
  Кривая без истории:10579
  Кривая без истории:10580
  Кривая без истории:10581
  Кривая без истории:10582
  Кривая без истории:10583
  Кривая без истории:10584
  Кривая без истории:10585
  Кривая без истории:10586
  Кривая без истории:10587
  Кривая без истории:10588
  Кривая без истории:10589
  Кривая без истории:10590
  Кривая без истории:10591
  Кривая без истории:10592
  Кривая без истории:10593
  Кривая без истории:10594
  Кривая без истории:10595
  Кривая без истории:10596
  Кривая без истории:10597
  Кривая без истории:10598
  Кривая без истории:10599
  Кривая без истории:10600
  Кривая без истории:10601
  Кривая без истории:10602
  Кривая без истории:10603
  Кривая без истории:10604
  Кривая без истории:10605
  Кривая без истории:10606
  Кривая без истории:10607
  Кривая без истории:10608
  Кривая без истории:10609
  Кривая без истории:10610
  Кривая без истории:10611
  Кривая без истории:10612
  Кривая без истории:10613
  Кривая без истории:10614
  Кривая без истории:10615
  Кривая без истории:10616
  Кривая без истории:10617
  Кривая без истории:10618
  Кривая без истории:10619
  Кривая без истории:10620
  Кривая без истории:10621
  Кривая без истории:10622
  Кривая без истории:10623
  Кривая без истории:10624
  Кривая без истории:10625
  Кривая без истории:10626
  Кривая без истории:10627
  Кривая без истории:10628
  Кривая без истории:10629
  Кривая без истории:10630
  Кривая без истории:10631
  Кривая без истории:10632
  Кривая без истории:10633
  Кривая без истории:10634
  Кривая без истории:10635
  Кривая без истории:10636
  Кривая без истории:10637
  Кривая без истории:10638
  Кривая без истории:10639
  Кривая без истории:10640
  Кривая без истории:10641
  Кривая без истории:10642
  Кривая без истории:10643
  Кривая без истории:10644
  Кривая без истории:10645
  Кривая без истории:10646
  Кривая без истории:10647
  Кривая без истории:10648
  Кривая без истории:10649
  Кривая без истории:10650
  Кривая без истории:10651
  Кривая без истории:10652
  Кривая без истории:10653
  Кривая без истории:10654
  Кривая без истории:10655
  Кривая без истории:10656
  Кривая без истории:10657
  Кривая без истории:10658
  Кривая без истории:10659
  Кривая без истории:10660
  Кривая без истории:10661
  Кривая без истории:10662
  Кривая без истории:10663
  Кривая без истории:10664
  Кривая без истории:10665
  Кривая без истории:10666
  Кривая без истории:10667
  Кривая без истории:10668
  Кривая без истории:10669
  Кривая без истории:10670
  Кривая без истории:10671
  Кривая без истории:10672
  Кривая без истории:10673
  Кривая без истории:10674
  Кривая без истории:10675
  Кривая без истории:10676
  Кривая без истории:10677
  Кривая без истории:10678
  Кривая без истории:10679
  Кривая без истории:10680
  Кривая без истории:10681
  Кривая без истории:10682
  Кривая без истории:10683
  Кривая без истории:10684
  Кривая без истории:10685
  Кривая без истории:10686
  Кривая без истории:10687
  Кривая без истории:10688
  Кривая без истории:10689
  Кривая без истории:10690
  Кривая без истории:10691
  Кривая без истории:10692
  Кривая без истории:10693
  Кривая без истории:10694
  Кривая без истории:10695
  Кривая без истории:10696
  Кривая без истории:10697
  Кривая без истории:10698
  Кривая без истории:10699
  Кривая без истории:10700
  Кривая без истории:10701
  Кривая без истории:10702
  Кривая без истории:10703
  Кривая без истории:10704
  Кривая без истории:10705
  Кривая без истории:10706
  Кривая без истории:10707
  Кривая без истории:10708
  Кривая без истории:10709
  Кривая без истории:10710
  Кривая без истории:10711
  Кривая без истории:10712
  Кривая без истории:10713
  Кривая без истории:10714
  Кривая без истории:10715
  Кривая без истории:10716
  Кривая без истории:10717
  Кривая без истории:10718
  Кривая без истории:10719
  Кривая без истории:10720
  Кривая без истории:10721
  Кривая без истории:10722
  Кривая без истории:10723
  Кривая без истории:10724
  Кривая без истории:10725
  Кривая без истории:10726
  Кривая без истории:10727
  Кривая без истории:10728
  Кривая без истории:10729
  Кривая без истории:10730
  Кривая без истории:10731
  Кривая без истории:10732
  Кривая без истории:10733
  Кривая без истории:10734
  Кривая без истории:10735
  Кривая без истории:10736
  Кривая без истории:10737
  Кривая без истории:10738
  Кривая без истории:10739
  Кривая без истории:10740
  Кривая без истории:10741
  Кривая без истории:10742
  Кривая без истории:10743
  Кривая без истории:10744
  Кривая без истории:10745
  Кривая без истории:10746
  Кривая без истории:10747
  Кривая без истории:10748
  Кривая без истории:10749
  Кривая без истории:10750
  Кривая без истории:10751
  Кривая без истории:10752
  Кривая без истории:10753
  Кривая без истории:10754
  Кривая без истории:10755
  Кривая без истории:10756
  Кривая без истории:10757
  Кривая без истории:10758
  Кривая без истории:10759
  Кривая без истории:10760
  Кривая без истории:10761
